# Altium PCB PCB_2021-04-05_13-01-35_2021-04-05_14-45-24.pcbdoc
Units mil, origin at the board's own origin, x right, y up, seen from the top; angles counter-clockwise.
Board outline 2165 x 2110 mil, 2 copper layers (Top Layer, Bottom Layer); 24 components, 26 nets, 89 pads, 8 vias.
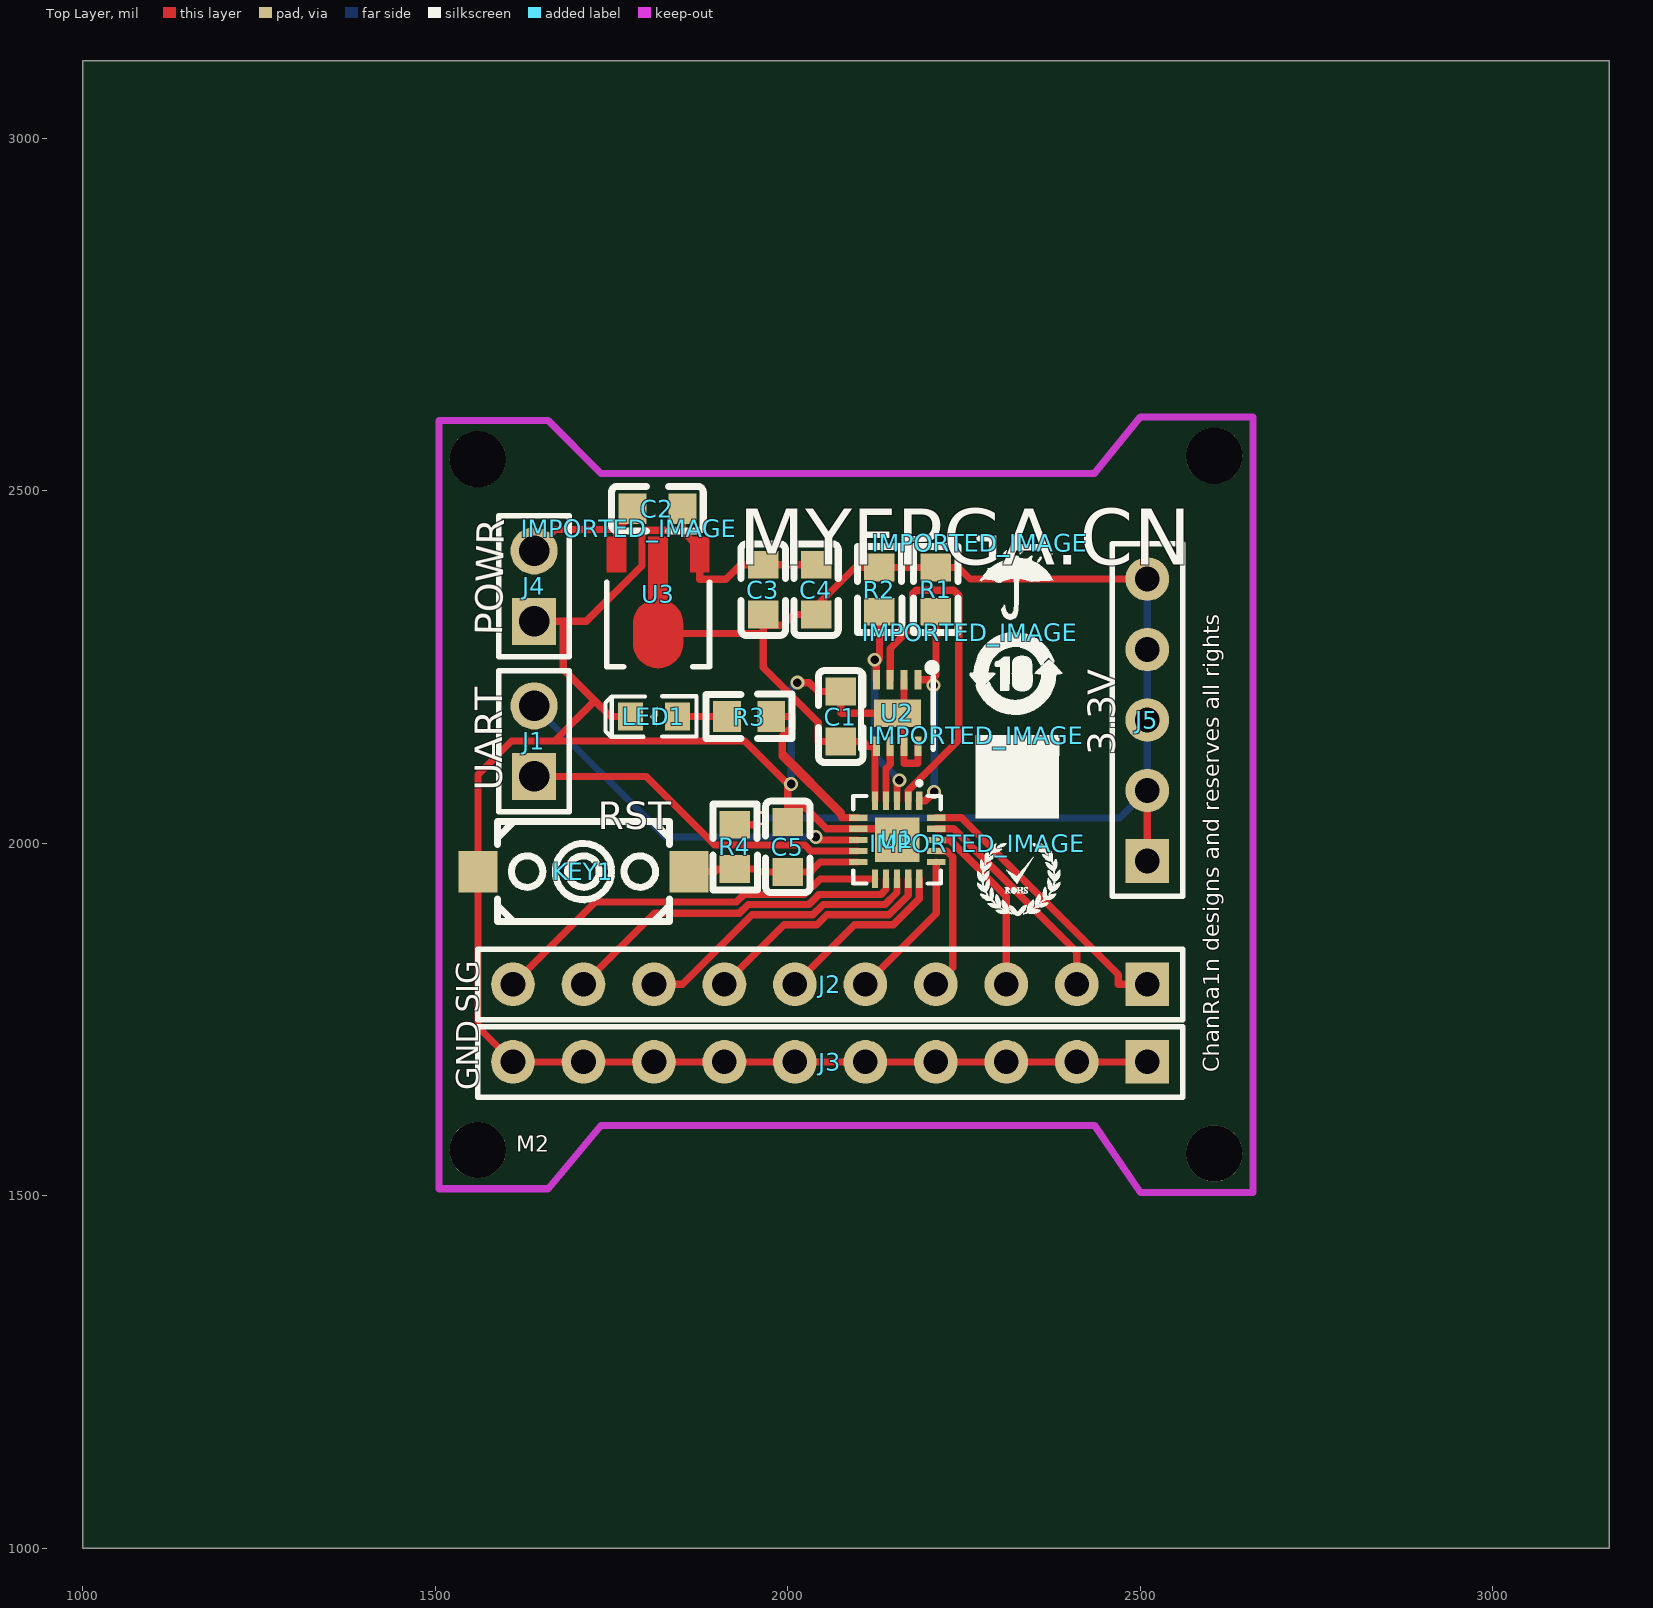
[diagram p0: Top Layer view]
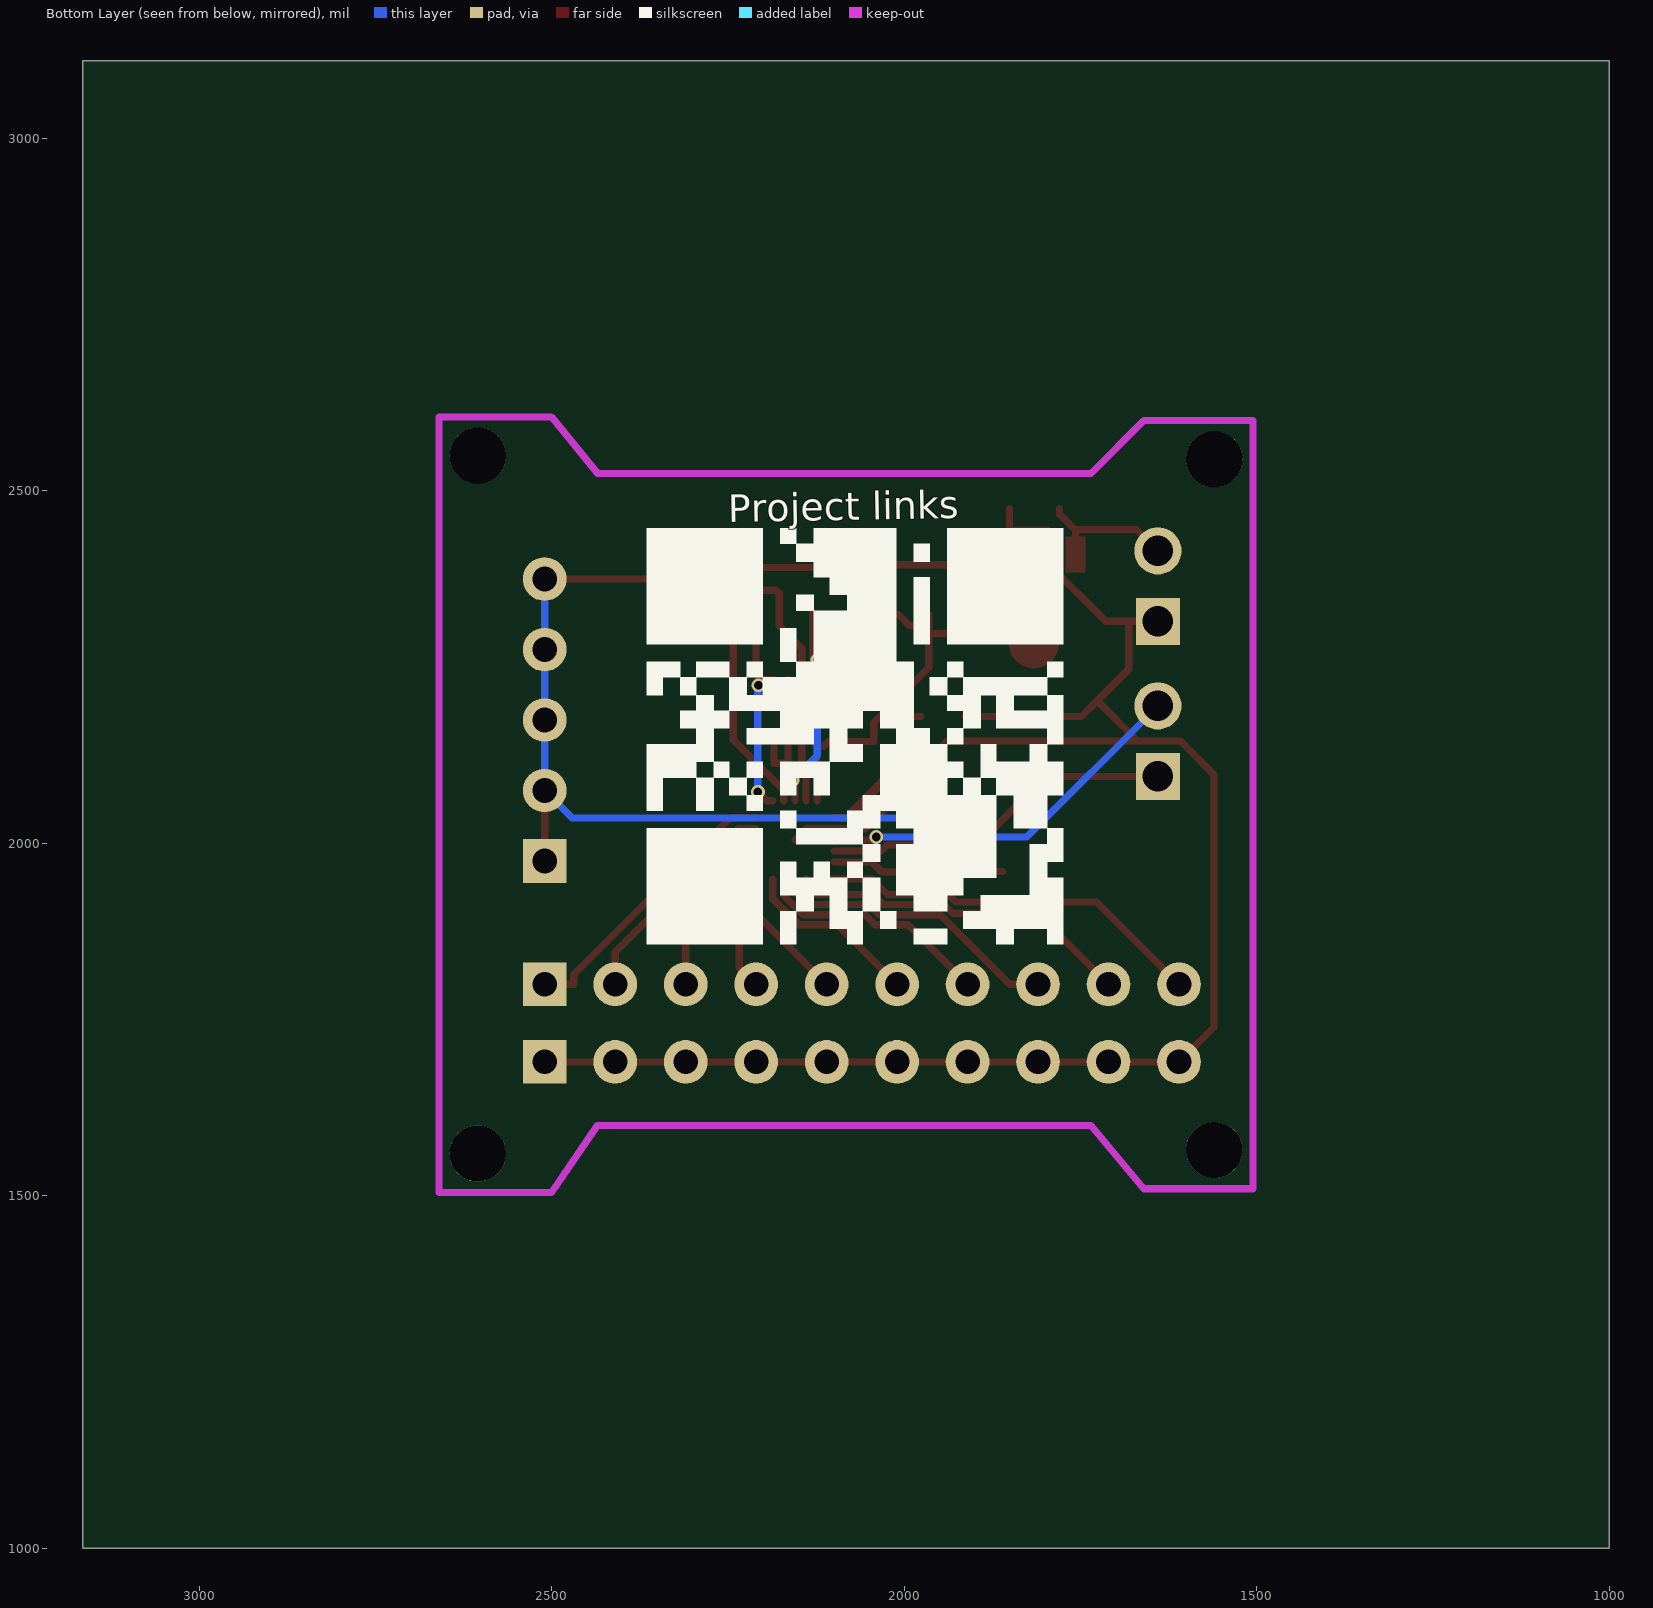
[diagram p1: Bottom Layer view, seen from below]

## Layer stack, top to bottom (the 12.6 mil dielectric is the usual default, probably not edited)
Top Layer: signal copper (thickness not stored)
Dielectric: dielectric 12.6, FR-4, Dk 4.8
Bottom Layer: signal copper (thickness not stored)

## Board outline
3165,1000 1000,1000 1000,3110 3165,3110

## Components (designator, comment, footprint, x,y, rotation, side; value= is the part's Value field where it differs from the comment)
C1 "0.1u" C0603 2075,2180 r270 top
C2 "1u" C0603 1815,2475 r180 top
C3 "4.7u" C0603 1965,2360 r270 top
C4 "0.1u" C0603 2040,2360 r270 top
C5 "0.1u" C0603 2000,1995 r270 top
IMPORTED_IMAGE "IMPORTED_IMAGE" IMPORTED_IMAGE 2268.39,2000.51 r0 top
IMPORTED_IMAGE "IMPORTED_IMAGE" IMPORTED_IMAGE 1774.45,2447.23 r0 top
IMPORTED_IMAGE "IMPORTED_IMAGE" IMPORTED_IMAGE 2266.74,2153.45 r0 top
IMPORTED_IMAGE "IMPORTED_IMAGE" IMPORTED_IMAGE 2258,2299.26 r0 top
IMPORTED_IMAGE "IMPORTED_IMAGE" IMPORTED_IMAGE 2272.17,2426.75 r0 top
J1 "HDR-M-2.54_1x2" HDR-M-2.54_1X2 1640,2145 r90 top
J2 "HDR-M-2.54_1x10" HDR-M-2.54_1X10 2060,1800 r180 top
J3 "HDR-M-2.54_1x10" HDR-M-2.54_1X10 2060,1690 r180 top
J4 "HDR-M-2.54_1x2" HDR-M-2.54_1X2 1640,2365 r90 top
J5 "HDR-M-2.54_1x5" HDR-M-2.54_1X5 2510,2175 r90 top
KEY1 "K2-3.6×6.1_SMD" KEY-SMD_2P-L6.2-W3.6-LS8.0 1710,1960 r0 top
LED1 "LED-0603_R" LED0603_RED 1810,2180 r180 top
R1 "1k" R0603 2210,2360 r90 top
R2 "1k" R0603 2130,2360 r270 top
R3 "1k" R0603 1945,2180 r0 top
R4 "1k" R0603 1925,1995 r270 top
U1 "STC8G1K08-38I-QFN20" TQFN-20L_L3.0-W3.0-P0.40-BL-EP 2155,2005 r180 top
U2 "SHT30-DIS-B" DFN-8_L2.5-W2.5-P0.50-BL-EP 2155,2185 r180 top
U3 "AMS1117-3.3" SOT-89 1875,2410 r270 top

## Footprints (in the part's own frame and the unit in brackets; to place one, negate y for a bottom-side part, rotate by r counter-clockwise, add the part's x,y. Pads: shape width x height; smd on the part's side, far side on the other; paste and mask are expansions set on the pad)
C0603 [mm]
  rect 1x1.1 smd: 1(-0.9,0) 2(0.9,0)
  silkscreen extent -1.65,-0.8 1.65,0.8
DFN-8_L2.5-W2.5-P0.50-BL-EP [mm]
  rect 0.25x0.7 smd: 1(-0.75,-1.2) 2(-0.25,-1.2) 3(0.25,-1.2) 4(0.75,-1.2) 5(0.75,1.2) 6(0.25,1.2) 7(-0.25,1.2) 8(-0.75,1.2)
  rect 1.7x1 smd: 9(-0.015,0.013)
  silkscreen extent -1.39,-1.77 1.3,1.3
HDR-M-2.54_1X2 [mm]
  rect 1.7x1.575 hole 1.1: 1(-1.27,0)
  round 1.7 hole 1.1: 2(1.27,0)
  silkscreen extent -2.54,-1.27 2.54,1.27
HDR-M-2.54_1X5 [mil]
  rect 62x62 hole 35: 1(-200,0)
  round 62 hole 35: 2(-100,0) 3(0,0) 4(100,0) 5(200,0)
  silkscreen extent -250,-50 250,50
HDR-M-2.54_1X10 [mil]
  rect 62x62 hole 35: 1(-450,0)
  round 62 hole 35: 2(-350,0) 3(-250,0) 4(-150,0) 5(-50,0) 6(50,0) 7(150,0) 8(250,0) 9(350,0) 10(450,0)
  silkscreen extent -500,-50 500,50
IMPORTED_IMAGE [mil]
  silkscreen extent 0,-103 118,0
KEY-SMD_2P-L6.2-W3.6-LS8.0 [mm]
  rect 1.4x1.5 smd: 1(-3.8,0) 2(3.8,0)
  silkscreen extent -3.1,-1.8 3.1,1.8
LED0603_RED [mm]
  rect 0.9x1 smd: 1(-0.85,0) 2(0.85,0)
  silkscreen extent -1.54,-0.73 1.75,0.73
R0603 [mm]
  rect 1x1.1 smd: 1(-0.8,0) 2(0.8,0)
  silkscreen extent -1.55,-0.8 1.55,0.81
SOT-89 [mm]
  round 0 smd: 1(0,0) 2(0.865,-1.5) 2(2.85,-1.5) 3(0,-3)
  Top Layer region: 2.5,-2.4 2.387,-2.393 2.276,-2.372 2.169,-2.337 2.067,-2.289 1.971,-2.228 1.884,-2.156 1.806,-2.074 1.74,-1.982 1.686,-1.883 1.644,-1.778 1.616,-1.669 1.602,-1.557 1.602,-1.443 1.616,-1.331 1.644,-1.222 1.686,-1.117 1.74,-1.018 1.806,-0.926 1.884,-0.844 1.971,-0.772 2.067,-0.711 2.169,-0.663 2.276,-0.628 2.387,-0.607 2.5,-0.6 3.2,-0.6 3.313,-0.607 3.424,-0.628 3.531,-0.663 3.633,-0.711 3.729,-0.772 3.816,-0.844 3.894,-0.926 3.96,-1.018 4.014,-1.117 4.056,-1.222 4.084,-1.331 4.098,-1.443 4.098,-1.557 4.084,-1.669 4.056,-1.778 4.014,-1.883 3.96,-1.982 3.894,-2.074 3.816,-2.156 3.729,-2.228 3.633,-2.289 3.531,-2.337 3.424,-2.372 3.313,-2.393 3.2,-2.4
  Top Layer region: 0.635,-2.65 0.635,-3.35 -0.635,-3.35 -0.635,-2.65
  Top Layer region: 0.635,0.35 0.635,-0.35 -0.635,-0.35 -0.635,0.35
  Top Layer region: 2.365,-1.15 2.365,-1.85 -0.635,-1.85 -0.635,-1.15
  silkscreen extent 1,-3.35 4.05,0.35
TQFN-20L_L3.0-W3.0-P0.40-BL-EP [mm]
  rect 0.224x0.665 smd: 1(-0.8,-1.407) 2(-0.4,-1.407) 3(0,-1.407) 4(0.4,-1.407) 5(0.8,-1.407) 11(0.8,1.407) 12(0.4,1.407) 13(0,1.407) 14(-0.4,1.407) 15(-0.8,1.407)
  rect 0.665x0.224 smd: 6(1.407,-0.8) 7(1.407,-0.4) 8(1.407,0) 9(1.407,0.4) 10(1.407,0.8) 16(-1.407,0.8) 17(-1.407,0.4) 18(-1.407,0) 19(-1.407,-0.4) 20(-1.407,-0.8)
  rect 1.6x1.6 smd: 21(0,0)
  silkscreen extent -1.58,-2.11 1.58,1.58

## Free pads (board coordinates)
  round 80 hole 80 unplated: ""(1560,1565) ""(1560,2545) ""(2605,1560) ""(2605,2550)

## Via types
v1: diameter 19.69, hole 12.2, Top Layer to Bottom Layer, 8 vias

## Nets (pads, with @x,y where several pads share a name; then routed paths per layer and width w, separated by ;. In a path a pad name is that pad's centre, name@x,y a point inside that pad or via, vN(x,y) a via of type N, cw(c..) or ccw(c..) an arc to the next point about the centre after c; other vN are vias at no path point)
3V3: C1.2 C3.2 C4.2 J5.1 J5.2 J5.3 J5.4 J5.5 R1.2 R2.1 R4.1 U1.5 U2.5 U3.2 | length 2206.7
  Top Layer w10.24: 1816,2375.9 1816,2297.8 1965,2297.8 ; R4.1 1956.9,2026.5 1956.9,2030.3 v1(1962.5,2035.9) ; C3.2 C3.2@1965,2309.6 ; C4.2 C4.2@2028.4,2324.6 ; U1.5 U2.5@2123.5,2137.7 ; U2.5@2125.5,2137.7 U2.5@2123.5,2137.7 ; J5.1 J5.2 ; J5.5 2258.4,2375 2241.9,2391.5 R1.2 R2.1 2095.3,2391.5 C4.2@2028.4,2324.6 ; 1965,2297.8 1965,2302.1 C3.2@1965,2309.6 ; 1965,2297.8 1965,2249.6 2043.1,2171.6 2043.1,2144.6 C1.2 2106.9,2144.6 2113.7,2137.7 U2.5@2123.5,2137.7 ; C3.2@1965,2309.6 1993.1,2309.6 2008.1,2324.6 2024,2324.6 C4.2@2028.4,2324.6
  Bottom Layer w10.24: v1(1962.5,2035.9) 2470.9,2035.9 J5.2 J5.3 J5.4 J5.5
GND: C1.1 C2.1 C3.1 C4.1 C5.1 J3.1 J3.2 J3.3 J3.4 J3.5 J3.6 J3.7 J3.8 J3.9 J3.10 J4.1 KEY1.1 LED1.2 U1.7 U1.21 U2.2 U2.7 U2.8 U2.9 U3.1 | length 3387.4
  Top Layer w10.24: J4.1 1681.3,2315 ; LED1.2 1762.5,2180 1748.5,2180 1726.1,2202.4 ; C2.1 1850.4,2447.2 1850.4,2444.2 ; C5.1 2000,2050.7 ; v1(2004.7,2084.2) v1@2000,2084.2 ; v1(2013.5,2228) 2030.5,2228 2043.1,2215.4 C1.1 2075,2209.5 2075,2185.5 2076,2184.5 U2.9 ; C4.1 C3.1 1949,2395.4 1933.1,2395.4 1912.4,2374.7 1875,2374.7 U3.1 1875,2418.5 1850.4,2443.1 1850.4,2444.2 ; U1.21 2139.3,2020.7 U1.7 2054.9,2020.7 2024.9,2050.7 2000,2050.7 ; U2.2 2164.8,2193.7 U2.9 ; U2.8@2184.5,2137.7 2184.5,2113.7 2164.8,2113.7 2164.8,2137.7 2164.8,2175.3 U2.9 ; J3.1 J3.2 J3.3 J3.4 J3.5 J3.6 J3.7 J3.8 J3.9 J3.10 1560.4,1739.6 KEY1.1 1560.4,2097.5 1608.1,2145.2 1668.9,2145.2 ; 1668.9,2145.2 1726.1,2202.4 ; 1668.9,2145.2 1939,2145.2 v1@2000,2084.2 ; 1681.3,2315 1714,2315 1793,2394 1793,2441.2 1796,2444.2 1850.4,2444.2 ; 1681.3,2315 1681.3,2247.2 1726.1,2202.4 ; 2000,2050.7 2000,2060.4 v1@2000,2084.2
  Bottom Layer w10.24: v1(2004.7,2084.2) 2004.7,2219.3 v1(2013.5,2228)
MCU_RST: C5.2 KEY1.2 R4.2 U1.10 | length 248.8
  Top Layer w10.24: KEY1.2 1897.4,1960 1900.9,1963.5 R4.2 1956.9,1963.5 1960.9,1959.6 C5.2 2016,1959.6 2031.9,1959.6 2045.9,1973.5 2076.2,1973.5 U1.10
R3_1: LED1.1 R3.1 | length 70
  Top Layer w10.24: LED1.1 1871.5,2180 R3.1
S$6710: 
S$6720: 
S$6722: 
S$6726: 
SHT30_ALERT: U1.2 U2.3 | length 526.9
  Top Layer w10.24: U2.3 2145.2,2276.4 2177.1,2308.3 2177.1,2354.3 2182,2359.2 2235.2,2359.2 2242.4,2352 2242.4,2146.7 2170.8,2075.1 U1.2@2170.8,2060.4
SHT30_RST: U1.4 U2.6 | length 79.7
  Top Layer w10.24: U1.4 2139.3,2105.9 2145.2,2111.9 U2.6@2145.2,2137.7
SHT30_SCL: R2.2 U1.3 U2.4 | length 319.4
  Top Layer w10.24: v1(2123.2,2260.5) 2125.5,2258.2 v1@2125.5,2256.3 ; U2.4 v1@2125.5,2256.3 ; R2.2 2130,2298.5 2130,2260.8 v1@2125.5,2256.3 ; U1.3 2155,2086.2 v1(2158.3,2089.5)
  Bottom Layer w10.24: v1(2123.2,2260.5) 2123.2,2124.5 v1(2158.3,2089.5)
SHT30_SDA: R1.1 U1.1 U2.1 | length 305.4
  Top Layer w10.24: U2.1 v1@2204.1,2232.2 ; U1.1 2195.1,2060.4 v1(2207.6,2072.9) ; v1(2206.7,2224.3) 2204.1,2226.8 v1@2204.1,2232.2 ; R1.1 2210,2298.5 2210,2238.1 v1@2204.1,2232.2
  Bottom Layer w10.24: v1(2206.7,2224.3) 2207.6,2223.4 v1(2207.6,2072.9)
U1_6: R3.2 U1.6 | length 425
  Top Layer w10.24: R3.2 2006.5,2180 ; U1.6 2076.2,2036.5 ; 1992.2,2152.3 1992.2,2128.2 2076.2,2043.4 2076.2,2036.5 ; 1992.2,2152.3 2000.5,2160.7 ; 1992.2,2152.3 2000.5,2160.7 ; 1992.2,2152.3 1992.2,2123.6 2076.2,2039.5 2076.2,2036.5 ; 2000.5,2160.7 2003.5,2160.7 ; 2000.5,2160.7 2003.5,2160.7 ; 2003.5,2160.7 2006.5,2163.7 ; 2003.5,2160.7 2006.5,2163.7 ; 2006.5,2163.7 2006.5,2180 ; 2006.5,2163.7 2006.5,2180
U1_8: J1.2 U1.8 | length 538.3
  Top Layer w10.24: v1(2039.6,2009.1) 2043.7,2005 U1.8
  Bottom Layer w10.24: J1.2 1825.9,2009.1 v1(2039.6,2009.1)
U1_9: J1.1 U1.9 | length 503.5
  Top Layer w10.24: J1.1 1681.3,2095 1799,2095 1896.3,1997.6 2024.2,1997.6 2032.6,1989.2 U1.9@2099.6,1989.2
U1_11: J2.10 U1.11 | length 575.5
  Top Layer w10.24: J2.10 1726.9,1916.9 1926.9,1916.9 1937.4,1927.3 2023.7,1927.3 2045.9,1949.6 U1.11
U1_12: J2.9 U1.12 | length 499.8
  Top Layer w10.24: J2.9 1810.9,1900.9 1931.1,1900.9 1943.3,1913.1 2029.6,1913.1 2043.9,1927.3 2131.7,1927.3 2139.3,1934.9 U1.12
U1_13: J2.8 U1.13 | length 418.2
  Top Layer w10.24: J2.8 1850.4,1800 1949.2,1898.8 2035.5,1898.8 2049.8,1913.1 2137.6,1913.1 2155,1930.4 U1.13
U1_14: J2.7 U1.14 | length 336.6
  Top Layer w10.24: J2.7 1994.5,1884.5 2041.4,1884.5 2055.7,1898.8 2143.5,1898.8 2170.8,1926 U1.14@2170.8,1949.6
U1_15: J2.6 U1.15 | length 254.9
  Top Layer w10.24: J2.6 2094.5,1884.5 2149.5,1884.5 2186.5,1921.5 2186.5,1926.2 U1.15
U1_16: J2.5 U1.16 | length 215.1
  Top Layer w10.24: J2.5 2210.4,1900.4 U1.16
U1_17: J2.4 U1.17 | length 217.7
  Top Layer w10.24: J2.4 2234,1824 2234,1980.6 2225.3,1989.2 U1.17@2210.4,1989.2
U1_18: J2.3 U1.18 | length 257.6
  Top Layer w10.24: U1.18 2229.8,2005 2310,1924.8 J2.3
U1_19: J2.2 U1.19 | length 317.9
  Top Layer w10.24: U1.19 2235.2,2020.7 2410,1845.9 J2.2
U1_20: J2.1 U1.20 | length 405.8
  Top Layer w10.24: U1.20 2233.8,2036.5 2246.3,2036.5 2468.7,1814.1 2468.7,1800 J2.1
VCC: C2.2 J4.2 U3.3 | length 205
  Top Layer w10.24: J4.2 1670.3,2445.3 1756.9,2445.3 1756.9,2444.2 ; U3.3 1756.9,2441.1 1756.9,2444.2 ; C2.2 1779.6,2466.8 1756.9,2444.2

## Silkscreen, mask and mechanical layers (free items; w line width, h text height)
Top Overlay:
  text "MYFPGA.CN" at 1930,2395 h80
  text "POWR" at 1594.68,2294.66 h39.37 r89
  text "3.3V" at 2464.68,2125 h39.37 r90
  text "UART" at 1594.68,2075 h39.37 r90
  text "RST" at 1730,2020.32 h39.37
  text "SIG" at 1560.75,1760 h31.5 r90
  text "ChanRa1n designs and reserves all rights" at 2620,1675 h39.37 r90
  text "GND" at 1560.75,1650 h31.5 r90
  text "M2" at 1615,1555 h39.37
Bottom Overlay:
  text "Project links" at 2249.66,2455.32 h39.37 r359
